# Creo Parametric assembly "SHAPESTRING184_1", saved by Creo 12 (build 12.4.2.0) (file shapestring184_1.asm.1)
Units: Custom; MM, KILOGRAM, SECS

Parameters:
  PTC_WM_ITERATION = "0"
  PTC_WM_VERSION = "-.0"
  PTC_WM_LIFECYCLE_STATE = "In Work"
  PTC_WM_LIFECYCLE = "MO_CADDocument"
  PTC_WM_CREATED_BY = "Maximilian Roepper (Z0017RMS: MO)"
  PTC_WM_CREATED_ON = "18-Sep-26 11:36:42 AM"
  PTC_WM_MODIFIED_BY = "Maximilian Roepper (Z0017RMS: MO)"
  PTC_WM_MODIFIED_ON = "18-Sep-26 11:36:46 AM"
  PDMLINKNUMBER = "PDM000071454767"
  PTC_WM_NUMBER = "PDM000071454767"

Other parameters: WEIGHT, WEIGHT_FACTOR, WEIGHT_ADD, MC_ERRORS, SUPPLIER

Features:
  1. coordinate system
  2. imported feature
  3. component "SHAPESTRING083_1"
  4. component "SHAPESTRING178_1"
  5. component "SHAPESTRING179_1"
  6. component "SHAPESTRING180_1"
  7. component "SHAPESTRING181_1"
  8. component "SHAPESTRING182_1"
  9. component "SHAPESTRING183_1"

Other named items: DRW_VIEW_ORG, ROUGH-GROB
